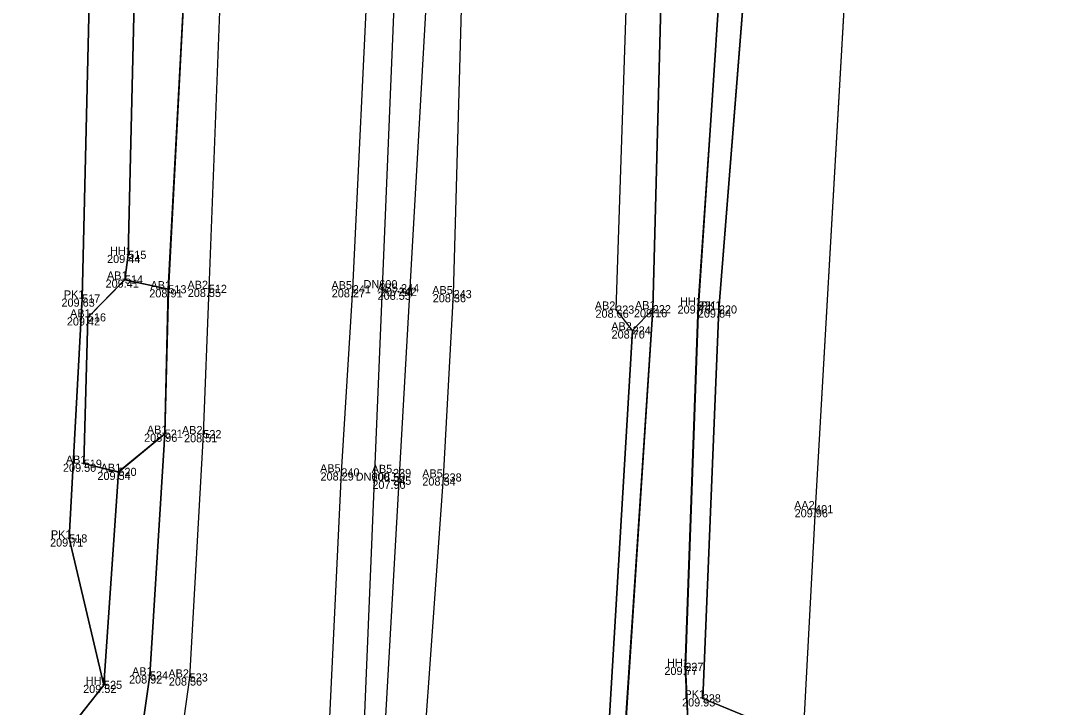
# Model space of a CAD drawing. Extents: x -263091 to -262565, y -1238731 to -1237092.
# Drawn here: x -262835.54 to -262810.24, y -1237925.36 to -1237908.46 of the extents above; entities that cross this region are included whole.
import ezdxf

# ---------------------------------------------------------------- set-up
doc = ezdxf.new("R2010")
doc.units = 0
for name, color, linetype in [('01_Hrana_betónu', 7, 'Continuous'), ('02_Oplotenie', 7, 'Continuous'), ('03_Asfalt', 7, 'Continuous'), ('05_Hrana_terénu', 7, 'Continuous'), ('07_Iné', 7, 'Continuous'), ('09_Múrik', 7, 'Continuous'), ('Groma (21)', 7, 'Continuous'), ('Groma (22)', 7, 'Continuous'), ('Groma (23)', 7, 'Continuous'), ('Groma (24)', 7, 'Continuous'), ('U004_Asfalty', 7, 'Continuous'), ('U004_Betónové_múriky', 7, 'Continuous'), ('U004_Betónové_panely', 7, 'Continuous'), ('U004_Betóny_prídavné', 7, 'Continuous'), ('U004_Zeleň_mimo', 7, 'Continuous'), ('U004_Zeleň_vnútro', 7, 'Continuous'), ('U004_Zeleň_zatrávňovač', 7, 'Continuous')]:
    doc.layers.add(name, color=color, linetype=linetype)

msp = doc.modelspace()

# ---------------------------------------------------------------- linework, layer by layer
at = {"layer": '01_Hrana_betónu'}
for points in [[(-262833.49, -1237932.513), (-262832.358, -1237924.572), (-262831.993, -1237918.626), (-262831.904, -1237915.074), (-262831.439, -1237906.309), (-262830.324, -1237884.482), (-262828.859, -1237869.656), (-262826.973, -1237856.487), (-262824.752, -1237845.872), (-262820.768, -1237827.409), (-262815.971, -1237805.011), (-262811.874, -1237785.528), (-262810.073, -1237767.205), (-262809.465, -1237744.209), (-262809.348, -1237719.32), (-262807.762, -1237709.127), (-262805.583, -1237701.261), (-262801.096, -1237689.829), (-262795.064, -1237676.268)], [(-262794.181, -1237676.612), (-262800.21, -1237690.201), (-262804.735, -1237701.618), (-262806.814, -1237709.415), (-262808.46, -1237719.391), (-262808.589, -1237744.23), (-262809.169, -1237767.262), (-262810.977, -1237785.858), (-262815.119, -1237805.286), (-262819.878, -1237827.449), (-262823.898, -1237846.237), (-262826.14, -1237856.747), (-262827.996, -1237869.725), (-262829.453, -1237884.611), (-262830.572, -1237906.318), (-262830.909, -1237915.064), (-262831.044, -1237918.638), (-262831.379, -1237924.623), (-262832.499, -1237932.636), (-262832.416, -1237932.646)], [(-262828.366, -1237932.946), (-262828.106, -1237929.217), (-262827.649, -1237919.578), (-262827.369, -1237915.073), (-262826.968, -1237906.664), (-262825.835, -1237884.909), (-262824.318, -1237870.338), (-262822.252, -1237856.88), (-262820.394, -1237847.242), (-262816.344, -1237828.005), (-262811.527, -1237806.128), (-262807.485, -1237786.652), (-262805.817, -1237767.526), (-262804.904, -1237743.876), (-262804.544, -1237721.54), (-262802.773, -1237710.111), (-262800.948, -1237703.699), (-262796.578, -1237692.416), (-262790.297, -1237678.834), (-262789.671, -1237677.512)], [(-262788.862, -1237677.903), (-262789.612, -1237679.5), (-262795.758, -1237692.783), (-262800.102, -1237704.105), (-262801.904, -1237710.319), (-262803.638, -1237721.631), (-262804.041, -1237743.855), (-262804.886, -1237767.666), (-262806.567, -1237786.84), (-262810.653, -1237806.707), (-262815.575, -1237828.361), (-262819.614, -1237847.41), (-262821.404, -1237856.927), (-262823.638, -1237870.532), (-262825.083, -1237884.947), (-262826.299, -1237906.725), (-262827.242, -1237929.453), (-262827.527, -1237933.008)], [(-262788.441, -1237678.106), (-262789.499, -1237680.304), (-262796.488, -1237695.789), (-262799.561, -1237704.378), (-262801.599, -1237711.648), (-262803.17, -1237722.277), (-262803.523, -1237744.912), (-262804.331, -1237767.555), (-262806.033, -1237786.907), (-262810.428, -1237808.027), (-262815.321, -1237829.941), (-262818.5, -1237845.545), (-262820.865, -1237857.635), (-262822.962, -1237871.266), (-262824.386, -1237885.795), (-262825.49, -1237906.658), (-262826.835, -1237930.337), (-262826.931, -1237933.053)], [(-262825.987, -1237933.123), (-262825.899, -1237930.36), (-262825.137, -1237919.703), (-262824.89, -1237915.193), (-262824.65, -1237906.715), (-262823.596, -1237885.855), (-262822.137, -1237871.403), (-262820.061, -1237857.781), (-262817.692, -1237845.812), (-262814.459, -1237830.149), (-262809.645, -1237808.205), (-262805.191, -1237787.117), (-262803.484, -1237767.641), (-262802.568, -1237744.998), (-262802.266, -1237722.317), (-262800.862, -1237712.121), (-262798.805, -1237704.616), (-262795.791, -1237696.17), (-262788.393, -1237679.964), (-262787.674, -1237678.477)], [(-262783.803, -1237680.361), (-262791.072, -1237697.733), (-262794.156, -1237706.196), (-262796.111, -1237713.494), (-262797.353, -1237722.795), (-262798.006, -1237745.028), (-262798.995, -1237767.834), (-262800.837, -1237788.066), (-262805.174, -1237808.895), (-262810.048, -1237831.05), (-262813.207, -1237846.368), (-262815.438, -1237858.025), (-262817.519, -1237871.503), (-262819.01, -1237885.889), (-262819.761, -1237906.843), (-262819.991, -1237915.564)], [(-262820.488, -1237916.085), (-262820.893, -1237915.574), (-262820.599, -1237906.725), (-262819.894, -1237885.916), (-262818.364, -1237871.361), (-262816.365, -1237858.042), (-262814.122, -1237846.343), (-262810.891, -1237830.85), (-262806.137, -1237808.69), (-262801.736, -1237787.923), (-262799.952, -1237767.772), (-262798.979, -1237744.912), (-262798.159, -1237722.635), (-262796.927, -1237713.21), (-262795.035, -1237705.927), (-262791.963, -1237697.425), (-262785.076, -1237681.215)]]:
    msp.add_lwpolyline(points, dxfattribs=at)
at = {"layer": '02_Oplotenie'}
for points in [[(-262834.343, -1237921.203), (-262834.024, -1237915.302), (-262833.812, -1237906.279), (-262832.732, -1237884.616), (-262831.151, -1237869.343), (-262829.251, -1237856.325), (-262826.951, -1237845.31), (-262823.094, -1237827.731), (-262817.951, -1237804.339), (-262814.023, -1237784.135), (-262812.336, -1237767.05), (-262811.754, -1237744.594), (-262811.555, -1237719.093), (-262809.863, -1237708.888), (-262807.835, -1237700.632), (-262803.244, -1237689.13), (-262797.291, -1237676.038)], [(-262782.476, -1237683.046), (-262789.338, -1237700.035), (-262791.92, -1237707.468), (-262793.68, -1237714.792), (-262794.853, -1237723.195), (-262795.698, -1237745.299), (-262796.564, -1237768.081), (-262798.719, -1237788.188), (-262802.852, -1237809.448), (-262807.527, -1237831.589), (-262810.764, -1237846.834), (-262812.842, -1237857.763), (-262814.888, -1237871.127), (-262816.319, -1237886.182), (-262816.945, -1237895.233), (-262817.687, -1237906.993), (-262818.366, -1237915.571), (-262818.764, -1237925.136)]]:
    msp.add_lwpolyline(points, dxfattribs=at)
at = {"layer": '03_Asfalt'}
msp.add_lwpolyline([(-262814.5, -1237895.481), (-262815.119, -1237905.177), (-262816.001, -1237920.483), (-262816.76, -1237934.791)], dxfattribs=at)
at = {"layer": '05_Hrana_terénu'}
for points in [[(-262796.037, -1237675.468), (-262802.307, -1237689.303), (-262806.908, -1237700.928), (-262808.861, -1237708.991), (-262810.491, -1237719.246), (-262810.648, -1237744.371), (-262811.212, -1237767.185), (-262812.78, -1237784.48), (-262817.048, -1237804.549), (-262821.958, -1237827.467), (-262825.893, -1237845.536), (-262828.436, -1237856.363), (-262830.087, -1237869.518), (-262831.495, -1237884.449), (-262832.703, -1237906.272), (-262832.889, -1237914.228), (-262832.974, -1237914.835)], [(-262819.123, -1237925.833), (-262819.193, -1237924.361), (-262818.874, -1237915.472), (-262818.289, -1237906.84), (-262817.033, -1237886.241), (-262815.506, -1237871.209), (-262813.693, -1237857.604), (-262811.493, -1237846.649), (-262808.389, -1237831.401), (-262803.328, -1237809.401), (-262799.108, -1237788.219), (-262797.264, -1237767.972), (-262796.32, -1237745.233), (-262795.609, -1237723.113), (-262794.587, -1237714.488), (-262792.775, -1237707.13), (-262790.198, -1237699.936), (-262783.238, -1237683.427), (-262781.933, -1237681.667), (-262781.499, -1237681.254)], [(-262833.13, -1237919.565), (-262833.486, -1237924.805), (-262834.418, -1237925.991)]]:
    msp.add_lwpolyline(points, dxfattribs=at)
at = {"layer": '07_Iné'}
msp.add_lwpolyline([(-262831.993, -1237918.626), (-262833.13, -1237919.565), (-262833.983, -1237919.364), (-262833.882, -1237915.765), (-262832.974, -1237914.835), (-262831.904, -1237915.074)], dxfattribs=at)
at = {"layer": '09_Múrik'}
for points in [[(-262819.991, -1237915.564), (-262820.655, -1237925.75), (-262821.327, -1237933.476)], [(-262821.581, -1237933.453), (-262821.074, -1237925.854), (-262820.488, -1237916.085)]]:
    msp.add_lwpolyline(points, dxfattribs=at)
at = {"layer": 'Groma (21)'}
for centre in [(-262832.889, -1237914.228), (-262832.974, -1237914.835), (-262831.904, -1237915.074), (-262830.909, -1237915.064), (-262827.369, -1237915.073), (-262826.241, -1237915.133), (-262826.182, -1237915.048), (-262824.89, -1237915.193), (-262834.024, -1237915.302), (-262818.874, -1237915.472), (-262833.882, -1237915.765), (-262820.893, -1237915.574), (-262819.991, -1237915.564), (-262818.366, -1237915.571), (-262820.488, -1237916.085), (-262831.993, -1237918.626), (-262831.044, -1237918.638), (-262833.983, -1237919.364), (-262833.13, -1237919.565), (-262827.649, -1237919.578), (-262826.379, -1237919.592), (-262826.375, -1237919.783), (-262825.137, -1237919.703), (-262816.001, -1237920.483), (-262834.343, -1237921.203), (-262819.193, -1237924.361), (-262832.358, -1237924.572), (-262831.379, -1237924.623), (-262833.486, -1237924.805), (-262818.764, -1237925.136)]:
    msp.add_circle(centre, 0.01, dxfattribs=at)
at = {"layer": 'U004_Asfalty'}
msp.add_lwpolyline([(-262818.76, -1237925.14), (-262818.37, -1237915.57), (-262817.69, -1237906.99), (-262816.95, -1237895.23), (-262814.5, -1237895.48), (-262815.12, -1237905.18), (-262816, -1237920.48), (-262816.76, -1237934.79), (-262818.3, -1237934.7), (-262817.69, -1237925.58)], close=True, dxfattribs=at)
msp.add_lwpolyline([(-262816.76, -1237934.79), (-262818.3, -1237934.7), (-262817.69, -1237925.58), (-262818.76, -1237925.14), (-262818.37, -1237915.57), (-262817.69, -1237906.99), (-262816.95, -1237895.23), (-262814.5, -1237895.48), (-262815.12, -1237905.18), (-262816, -1237920.48), (-262816.76, -1237934.79)], dxfattribs=at)
at = {"layer": 'U004_Betónové_múriky'}
msp.add_lwpolyline([(-262820.66, -1237925.75), (-262821.33, -1237933.48), (-262821.58, -1237933.45), (-262821.07, -1237925.85), (-262820.49, -1237916.09), (-262819.99, -1237915.56)], close=True, dxfattribs=at)
msp.add_lwpolyline([(-262821.33, -1237933.48), (-262821.58, -1237933.45), (-262821.07, -1237925.85), (-262820.49, -1237916.09), (-262819.99, -1237915.56), (-262820.66, -1237925.75), (-262821.33, -1237933.48)], dxfattribs=at)
at = {"layer": 'U004_Betónové_panely'}
for points in [[(-262796.11, -1237713.49), (-262797.35, -1237722.8), (-262798.01, -1237745.03), (-262799, -1237767.83), (-262800.84, -1237788.07), (-262805.17, -1237808.9), (-262810.05, -1237831.05), (-262813.21, -1237846.37), (-262815.44, -1237858.03), (-262817.52, -1237871.5), (-262819.01, -1237885.89), (-262819.76, -1237906.84), (-262819.99, -1237915.56), (-262820.49, -1237916.09), (-262821.07, -1237925.85), (-262821.58, -1237933.45), (-262821.86, -1237933.43), (-262822, -1237934.47)], [(-262822, -1237934.47), (-262826.02, -1237934.23), (-262826.97, -1237934.17), (-262827.62, -1237934.13), (-262828.45, -1237934.08), (-262832.51, -1237933.84), (-262832.42, -1237932.65), (-262832.5, -1237932.64), (-262833.49, -1237932.51), (-262832.36, -1237924.57), (-262831.99, -1237918.63), (-262831.9, -1237915.07), (-262831.44, -1237906.31), (-262830.32, -1237884.48), (-262828.86, -1237869.66), (-262826.97, -1237856.49), (-262824.75, -1237845.87), (-262820.77, -1237827.41), (-262815.97, -1237805.01), (-262811.87, -1237785.53), (-262810.07, -1237767.21), (-262809.47, -1237744.21), (-262809.35, -1237719.32)], [(-262817.52, -1237871.5), (-262819.01, -1237885.89), (-262819.76, -1237906.84), (-262819.99, -1237915.56), (-262820.49, -1237916.09), (-262821.07, -1237925.85), (-262821.58, -1237933.45), (-262821.86, -1237933.43), (-262822, -1237934.47), (-262826.02, -1237934.23), (-262826.97, -1237934.17), (-262827.62, -1237934.13), (-262828.45, -1237934.08), (-262832.51, -1237933.84), (-262832.42, -1237932.65), (-262832.5, -1237932.64), (-262833.49, -1237932.51), (-262832.36, -1237924.57), (-262831.99, -1237918.63), (-262831.9, -1237915.07), (-262831.44, -1237906.31), (-262830.32, -1237884.48), (-262828.86, -1237869.66)]]:
    msp.add_lwpolyline(points, dxfattribs=at)
at = {"layer": 'U004_Betóny_prídavné'}
msp.add_lwpolyline([(-262831.9, -1237915.07), (-262831.99, -1237918.63), (-262833.13, -1237919.57), (-262833.98, -1237919.36), (-262833.88, -1237915.77), (-262832.97, -1237914.84)], close=True, dxfattribs=at)
msp.add_lwpolyline([(-262833.13, -1237919.57), (-262833.98, -1237919.36), (-262833.88, -1237915.77), (-262832.97, -1237914.84), (-262831.9, -1237915.07), (-262831.99, -1237918.63), (-262833.13, -1237919.57)], dxfattribs=at)
at = {"layer": 'U004_Zeleň_mimo'}
msp.add_lwpolyline([(-262831.15, -1237869.34), (-262832.73, -1237884.62), (-262833.81, -1237906.28), (-262834.02, -1237915.3), (-262834.34, -1237921.2), (-262833.49, -1237924.81), (-262834.42, -1237925.99), (-262837.15, -1237925.73), (-262837.41, -1237925.56), (-262839.28, -1237924.72), (-262838.95, -1237919.22), (-262848.49, -1237918.39), (-262860.57, -1237917.21), (-262859.39, -1237895.81), (-262865.89, -1237895.46), (-262864.07, -1237848.35)], dxfattribs=at)
at = {"layer": 'U004_Zeleň_vnútro'}
for points in [[(-262819.12, -1237925.83), (-262819.19, -1237924.36), (-262818.87, -1237915.47), (-262818.29, -1237906.84), (-262817.03, -1237886.24), (-262815.51, -1237871.21), (-262813.69, -1237857.6), (-262811.49, -1237846.65), (-262808.39, -1237831.4), (-262803.33, -1237809.4), (-262799.11, -1237788.22), (-262797.26, -1237767.97), (-262796.32, -1237745.23), (-262795.61, -1237723.11), (-262794.59, -1237714.49)], [(-262793.68, -1237714.79), (-262794.85, -1237723.2), (-262795.7, -1237745.3), (-262796.56, -1237768.08), (-262798.72, -1237788.19), (-262802.85, -1237809.45), (-262807.53, -1237831.59), (-262810.76, -1237846.83), (-262812.84, -1237857.76), (-262814.89, -1237871.13), (-262816.32, -1237886.18), (-262816.95, -1237895.23), (-262817.69, -1237906.99), (-262818.37, -1237915.57), (-262818.76, -1237925.14), (-262817.69, -1237925.58), (-262819.12, -1237925.83)], [(-262833.49, -1237924.81), (-262834.34, -1237921.2), (-262834.02, -1237915.3), (-262833.81, -1237906.28), (-262832.73, -1237884.62), (-262831.15, -1237869.34), (-262829.25, -1237856.33), (-262826.95, -1237845.31), (-262823.09, -1237827.73), (-262817.95, -1237804.34), (-262814.02, -1237784.14), (-262812.34, -1237767.05), (-262811.75, -1237744.59), (-262811.56, -1237719.09)], [(-262810.49, -1237719.25), (-262810.65, -1237744.37), (-262811.21, -1237767.19), (-262812.78, -1237784.48), (-262817.05, -1237804.55), (-262821.96, -1237827.47), (-262825.89, -1237845.54), (-262828.44, -1237856.36), (-262830.09, -1237869.52), (-262831.5, -1237884.45), (-262832.7, -1237906.27), (-262832.89, -1237914.23), (-262832.97, -1237914.84), (-262833.88, -1237915.77), (-262833.98, -1237919.36), (-262833.13, -1237919.57), (-262833.49, -1237924.81)], [(-262802.85, -1237809.45), (-262807.53, -1237831.59), (-262810.76, -1237846.83), (-262812.84, -1237857.76), (-262814.89, -1237871.13), (-262816.32, -1237886.18), (-262816.95, -1237895.23), (-262817.69, -1237906.99), (-262818.37, -1237915.57), (-262818.76, -1237925.14), (-262817.69, -1237925.58), (-262819.12, -1237925.83), (-262819.19, -1237924.36), (-262818.87, -1237915.47), (-262818.29, -1237906.84), (-262817.03, -1237886.24), (-262815.51, -1237871.21), (-262813.69, -1237857.6), (-262811.49, -1237846.65), (-262808.39, -1237831.4), (-262803.33, -1237809.4)], [(-262821.96, -1237827.47), (-262825.89, -1237845.54), (-262828.44, -1237856.36), (-262830.09, -1237869.52), (-262831.5, -1237884.45), (-262832.7, -1237906.27), (-262832.89, -1237914.23), (-262832.97, -1237914.84), (-262833.88, -1237915.77), (-262833.98, -1237919.36), (-262833.13, -1237919.57), (-262833.49, -1237924.81), (-262834.34, -1237921.2), (-262834.02, -1237915.3), (-262833.81, -1237906.28), (-262832.73, -1237884.62), (-262831.15, -1237869.34), (-262829.25, -1237856.33), (-262826.95, -1237845.31), (-262823.09, -1237827.73)]]:
    msp.add_lwpolyline(points, dxfattribs=at)
at = {"layer": 'U004_Zeleň_zatrávňovač'}
for points in [[(-262820.84, -1237933.52), (-262821.33, -1237933.48), (-262821.28, -1237933), (-262820.66, -1237925.75), (-262819.99, -1237915.56), (-262819.76, -1237906.84), (-262819.01, -1237885.89), (-262817.52, -1237871.5), (-262815.44, -1237858.03), (-262813.21, -1237846.37), (-262810.05, -1237831.05), (-262805.17, -1237808.9), (-262800.84, -1237788.07), (-262799, -1237767.83), (-262798.01, -1237745.03), (-262797.35, -1237722.8), (-262796.11, -1237713.49)], [(-262794.59, -1237714.49), (-262795.61, -1237723.11), (-262796.32, -1237745.23), (-262797.26, -1237767.97), (-262799.11, -1237788.22), (-262803.33, -1237809.4), (-262808.39, -1237831.4), (-262811.49, -1237846.65), (-262813.69, -1237857.6), (-262815.51, -1237871.21), (-262817.03, -1237886.24), (-262818.29, -1237906.84), (-262818.87, -1237915.47), (-262819.19, -1237924.36), (-262819.12, -1237925.83), (-262819.49, -1237933.29), (-262820.8, -1237933.2), (-262820.84, -1237933.52)], [(-262831.9, -1237915.07), (-262832.97, -1237914.84), (-262832.89, -1237914.23), (-262832.7, -1237906.27), (-262831.5, -1237884.45), (-262830.09, -1237869.52), (-262828.44, -1237856.36), (-262825.89, -1237845.54), (-262821.96, -1237827.47), (-262817.05, -1237804.55), (-262812.78, -1237784.48), (-262811.21, -1237767.19), (-262810.65, -1237744.37), (-262810.49, -1237719.25)], [(-262809.35, -1237719.32), (-262809.47, -1237744.21), (-262810.07, -1237767.21), (-262811.87, -1237785.53), (-262815.97, -1237805.01), (-262820.77, -1237827.41), (-262824.75, -1237845.87), (-262826.97, -1237856.49), (-262828.86, -1237869.66), (-262830.32, -1237884.48), (-262831.44, -1237906.31), (-262831.9, -1237915.07)], [(-262803.33, -1237809.4), (-262808.39, -1237831.4), (-262811.49, -1237846.65), (-262813.69, -1237857.6), (-262815.51, -1237871.21), (-262817.03, -1237886.24), (-262818.29, -1237906.84), (-262818.87, -1237915.47), (-262819.19, -1237924.36), (-262819.12, -1237925.83), (-262819.49, -1237933.29), (-262820.8, -1237933.2), (-262820.84, -1237933.52), (-262821.33, -1237933.48), (-262821.28, -1237933), (-262820.66, -1237925.75), (-262819.99, -1237915.56), (-262819.76, -1237906.84), (-262819.01, -1237885.89), (-262817.52, -1237871.5), (-262815.44, -1237858.03), (-262813.21, -1237846.37), (-262810.05, -1237831.05), (-262805.17, -1237808.9)], [(-262820.77, -1237827.41), (-262824.75, -1237845.87), (-262826.97, -1237856.49), (-262828.86, -1237869.66), (-262830.32, -1237884.48), (-262831.44, -1237906.31), (-262831.9, -1237915.07), (-262832.97, -1237914.84), (-262832.89, -1237914.23), (-262832.7, -1237906.27), (-262831.5, -1237884.45), (-262830.09, -1237869.52), (-262828.44, -1237856.36), (-262825.89, -1237845.54), (-262821.96, -1237827.47)], [(-262833.46, -1237932.25), (-262834.77, -1237932.05), (-262834.42, -1237925.99), (-262833.49, -1237924.81), (-262833.13, -1237919.57), (-262831.99, -1237918.63), (-262832.36, -1237924.57), (-262833.46, -1237932.25)]]:
    msp.add_lwpolyline(points, dxfattribs=at)
msp.add_lwpolyline([(-262834.42, -1237925.99), (-262833.49, -1237924.81), (-262833.13, -1237919.57), (-262831.99, -1237918.63), (-262832.36, -1237924.57), (-262833.46, -1237932.25), (-262834.77, -1237932.05)], close=True, dxfattribs=at)

# ---------------------------------------------------------------- texts
at = {"layer": 'Groma (22)'}
for s, p in [('515', (-262832.889, -1237914.328)), ('514', (-262832.974, -1237914.935)), ('513', (-262831.904, -1237915.174)), ('512', (-262830.909, -1237915.164)), ('241', (-262827.369, -1237915.173)), ('244', (-262826.182, -1237915.148)), ('517', (-262834.024, -1237915.402)), ('242', (-262826.241, -1237915.233)), ('243', (-262824.89, -1237915.293)), ('223', (-262820.893, -1237915.674)), ('222', (-262819.991, -1237915.664)), ('221', (-262818.874, -1237915.572)), ('220', (-262818.366, -1237915.671)), ('516', (-262833.882, -1237915.865)), ('224', (-262820.488, -1237916.185)), ('521', (-262831.993, -1237918.726)), ('522', (-262831.044, -1237918.738)), ('519', (-262833.983, -1237919.464)), ('520', (-262833.13, -1237919.665)), ('240', (-262827.649, -1237919.678)), ('239', (-262826.379, -1237919.692)), ('245', (-262826.375, -1237919.883)), ('238', (-262825.137, -1237919.803)), ('401', (-262816.001, -1237920.583)), ('518', (-262834.343, -1237921.303)), ('227', (-262819.193, -1237924.461)), ('524', (-262832.358, -1237924.672)), ('523', (-262831.379, -1237924.723)), ('525', (-262833.486, -1237924.905)), ('228', (-262818.764, -1237925.236))]:
    msp.add_text(s, height=0.2, dxfattribs=at).set_placement(p)
at = {"layer": 'Groma (23)'}
for s, p in [('209.44', (-262833.41, -1237914.428)), ('209.41', (-262833.447, -1237915.035)), ('208.91', (-262832.372, -1237915.274)), ('208.55', (-262831.426, -1237915.264)), ('208.27', (-262827.886, -1237915.273)), ('208.55', (-262826.758, -1237915.333)), ('207.94', (-262826.699, -1237915.248)), ('208.36', (-262825.402, -1237915.393)), ('209.63', (-262834.531, -1237915.502)), ('209.76', (-262819.382, -1237915.672)), ('209.42', (-262834.399, -1237915.965)), ('208.66', (-262821.4, -1237915.774)), ('209.16', (-262820.455, -1237915.764)), ('209.84', (-262818.883, -1237915.771)), ('208.70', (-262821.005, -1237916.285)), ('208.96', (-262832.5, -1237918.826)), ('208.51', (-262831.517, -1237918.838)), ('209.50', (-262834.494, -1237919.564)), ('209.54', (-262833.647, -1237919.765)), ('208.29', (-262828.161, -1237919.778)), ('208.50', (-262826.895, -1237919.792)), ('207.90', (-262826.887, -1237919.983)), ('208.34', (-262825.658, -1237919.903)), ('209.96', (-262816.503, -1237920.683)), ('209.71', (-262834.812, -1237921.403)), ('209.77', (-262819.706, -1237924.561)), ('208.92', (-262832.87, -1237924.772)), ('208.56', (-262831.891, -1237924.823)), ('209.52', (-262833.998, -1237925.005)), ('209.93', (-262819.271, -1237925.336))]:
    msp.add_text(s, height=0.2, dxfattribs=at).set_placement(p)
at = {"layer": 'Groma (24)'}
for s, p in [('HH1', (-262833.336, -1237914.228)), ('AB1', (-262833.412, -1237914.835)), ('AB1', (-262832.342, -1237915.074)), ('AB2', (-262831.433, -1237915.064)), ('AB5', (-262827.893, -1237915.073)), ('DN600', (-262827.103, -1237915.048)), ('AB5', (-262826.765, -1237915.133)), ('AB5', (-262825.414, -1237915.193)), ('PK1', (-262834.471, -1237915.302)), ('AB2', (-262821.417, -1237915.574)), ('AB1', (-262820.429, -1237915.564)), ('HH1', (-262819.321, -1237915.472)), ('PK1', (-262818.813, -1237915.571)), ('AB1', (-262834.32, -1237915.765)), ('AB2', (-262821.012, -1237916.085)), ('AB1', (-262832.431, -1237918.626)), ('AB2', (-262831.568, -1237918.638)), ('AB1', (-262834.421, -1237919.364)), ('AB1', (-262833.568, -1237919.565)), ('AB5', (-262828.173, -1237919.578)), ('AB5', (-262826.903, -1237919.592)), ('AB5', (-262825.661, -1237919.703)), ('DN600', (-262827.296, -1237919.783)), ('AA2', (-262816.516, -1237920.483)), ('PK1', (-262834.79, -1237921.203)), ('AB1', (-262832.796, -1237924.572)), ('HH1', (-262819.64, -1237924.361)), ('HH1', (-262833.933, -1237924.805)), ('AB2', (-262831.903, -1237924.623)), ('PK1', (-262819.211, -1237925.136))]:
    msp.add_text(s, height=0.2, dxfattribs=at).set_placement(p)

doc.saveas('drawing.dxf')
